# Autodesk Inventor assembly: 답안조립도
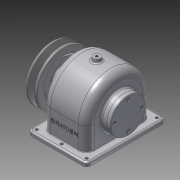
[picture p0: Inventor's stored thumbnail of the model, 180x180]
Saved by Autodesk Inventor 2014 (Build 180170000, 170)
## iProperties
Created: 2015-09
Part Number: 답안조립도
Document SubType Name: Assembly
Designer: Owner
Author: Owner
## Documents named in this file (14)
- C:\Documents and Settings\Owner\바탕 화면\450907V1022\답안조립도.iam
- C:\Documents and Settings\Owner\바탕 화면\450907V1022\1.본체.ipt
- C:\Documents and Settings\Owner\바탕 화면\450907V1022\앞커버.ipt
- C:\Documents and Settings\Owner\바탕 화면\450907V1022\뒤커버.ipt
- C:\Documents and Settings\Owner\바탕 화면\450907V1022\볼트 M3 x 8.ipt
- C:\Documents and Settings\Owner\바탕 화면\450907V1022\베어링 6203.ipt
- C:\Documents and Settings\Owner\바탕 화면\450907V1022\축.ipt
- C:\Documents and Settings\Owner\바탕 화면\450907V1022\키 - 6 x 6 x 22.ipt
- C:\Documents and Settings\Owner\바탕 화면\450907V1022\스퍼기어.ipt
- C:\Documents and Settings\Owner\바탕 화면\450907V1022\볼트 M3 x 10.ipt
- C:\Documents and Settings\Owner\바탕 화면\450907V1022\오일 실 17 32 8.ipt
- C:\Documents and Settings\Owner\바탕 화면\450907V1022\멈춤나사 - M4x10.ipt
- C:\Documents and Settings\Owner\바탕 화면\450907V1022\키 - 5 x 5 x 18.ipt
- C:\Documents and Settings\Owner\바탕 화면\450907V1022\V-벨트풀리.ipt
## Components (10 placed, 4 different names)
1. 1.본체:1
2. V-벨트풀리:1 — 각도:4
3. ISO 4762 M3 x 8:1
4. ISO 4762 M3 x 8:2
5. ISO 4762 M3 x 8:3
6. ISO 4762 M3 x 8:4
7. ISO 4762 M3 x 10:1
8. ISO 4762 M3 x 10:2
9. ISO 4762 M3 x 10:3
10. ISO 4762 M3 x 10:4
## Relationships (1: Angle 1)
- 각도:4 [Angle]: V-벨트풀리:1
